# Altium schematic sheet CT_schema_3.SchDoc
size 297 x 173 mm
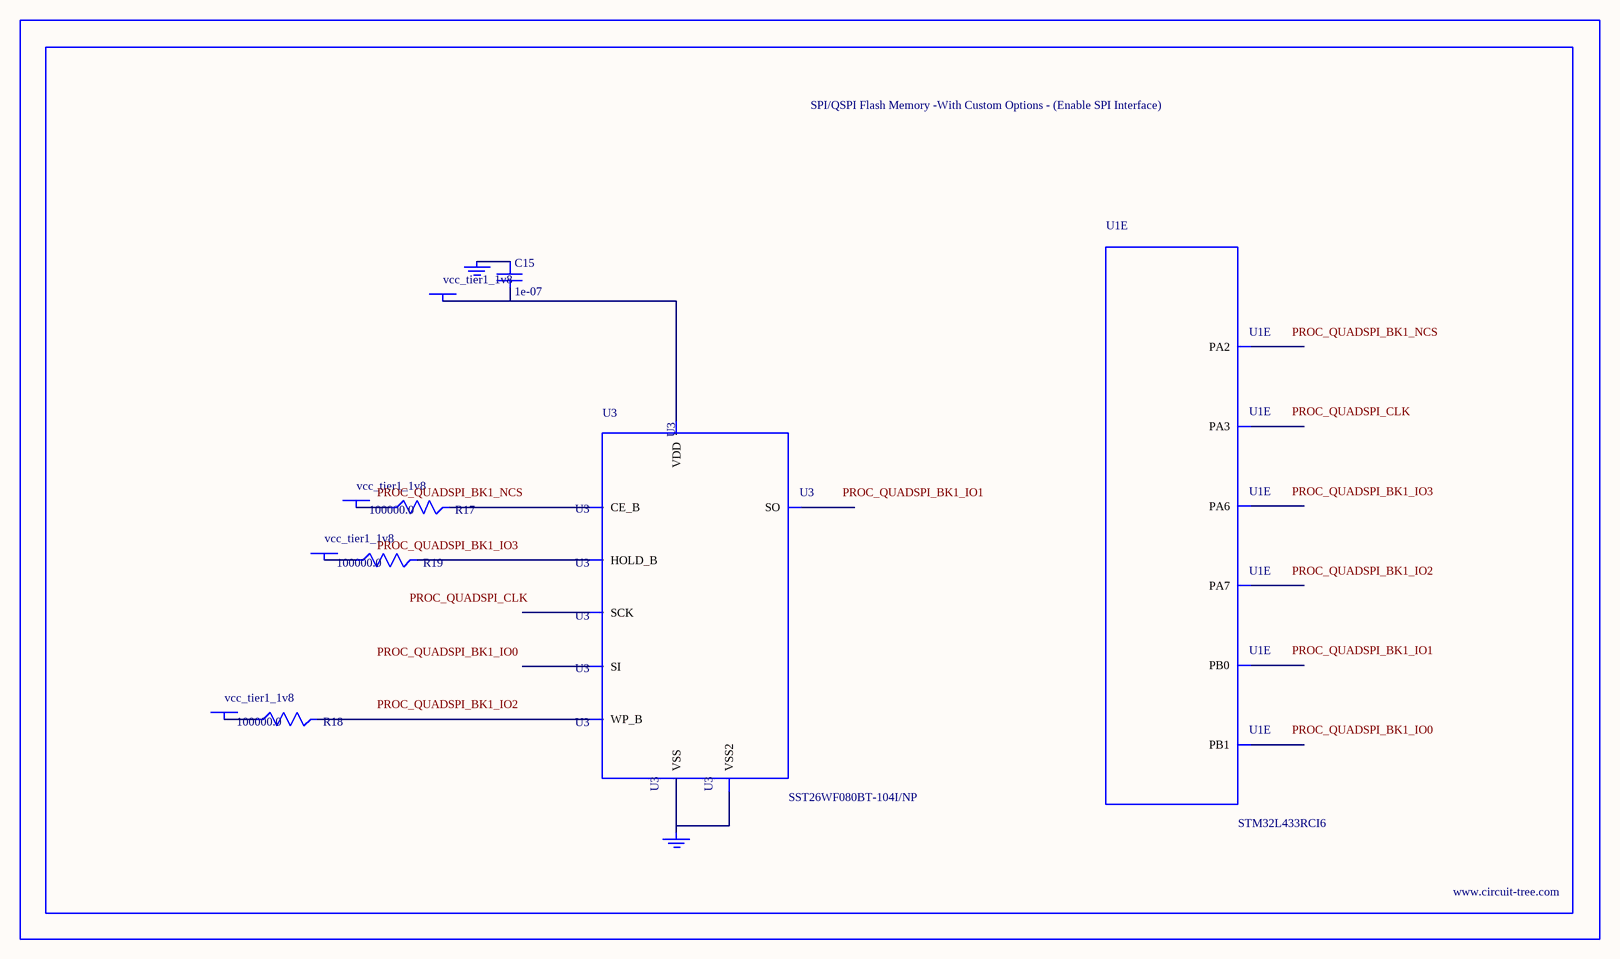
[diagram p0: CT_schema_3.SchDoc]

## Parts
BORDER2  (no value)
C15  1e-07  [C0402]
GND_INSTANCE_2_0  (no value)
GND_INSTANCE_2_1  (no value)
POWER_INSTANCE_2_0  vcc_tier1_1v8
POWER_INSTANCE_2_1  vcc_tier1_1v8
POWER_INSTANCE_2_2  vcc_tier1_1v8
POWER_INSTANCE_2_3  vcc_tier1_1v8
R17  100000.0  [R0603]
R18  100000.0  [R0603]
R19  100000.0  [R0603]
U1  STM32L433RCI6  [UFBGA64]  (part E of 7)
U3  SST26WF080BT-104I/NP  [USON-8]

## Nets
NetC15_1: C15.1 GND_INSTANCE_2_0.0(GND)
NetC15_2: C15.2 POWER_INSTANCE_2_3.0(PWR) U3.8(VDD)
NetGND_INSTANCE_2_1_0: GND_INSTANCE_2_1.0(GND) U3.4(VSS) U3.9(VSS2)
NetPOWER_INSTANCE_2_0_0: POWER_INSTANCE_2_0.0(PWR) R17.1
NetPOWER_INSTANCE_2_1_0: POWER_INSTANCE_2_1.0(PWR) R18.1
NetPOWER_INSTANCE_2_2_0: POWER_INSTANCE_2_2.0(PWR) R19.1
NetR17_2: R17.2 U3.1(CE_B)
NetR18_2: R18.2 U3.3(WP_B)
NetR19_2: R19.2 U3.7(HOLD_B)

Not connected (* = marked no-connect by the designer): U1 F3(PA2) F5(PB0) G3(PA3) G4(PA6) G5(PB1) H4(PA7); U3 2(SO) 5(SI) 6(SCK)

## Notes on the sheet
- Labels drawn without touching a wire or pin: PROC_QUADSPI_BK1_IO0, PROC_QUADSPI_BK1_IO1, PROC_QUADSPI_BK1_IO2, PROC_QUADSPI_BK1_IO3, PROC_QUADSPI_BK1_NCS, PROC_QUADSPI_CLK

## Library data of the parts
BORDER2 = BORDER_PAGE2
C15 = C0402C104K3RACTU
GND_INSTANCE_2_0 GND_INSTANCE_2_1 = GND
POWER_INSTANCE_2_0-POWER_INSTANCE_2_3 = PWR
R17-R19 = RC0603JR-07100KL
